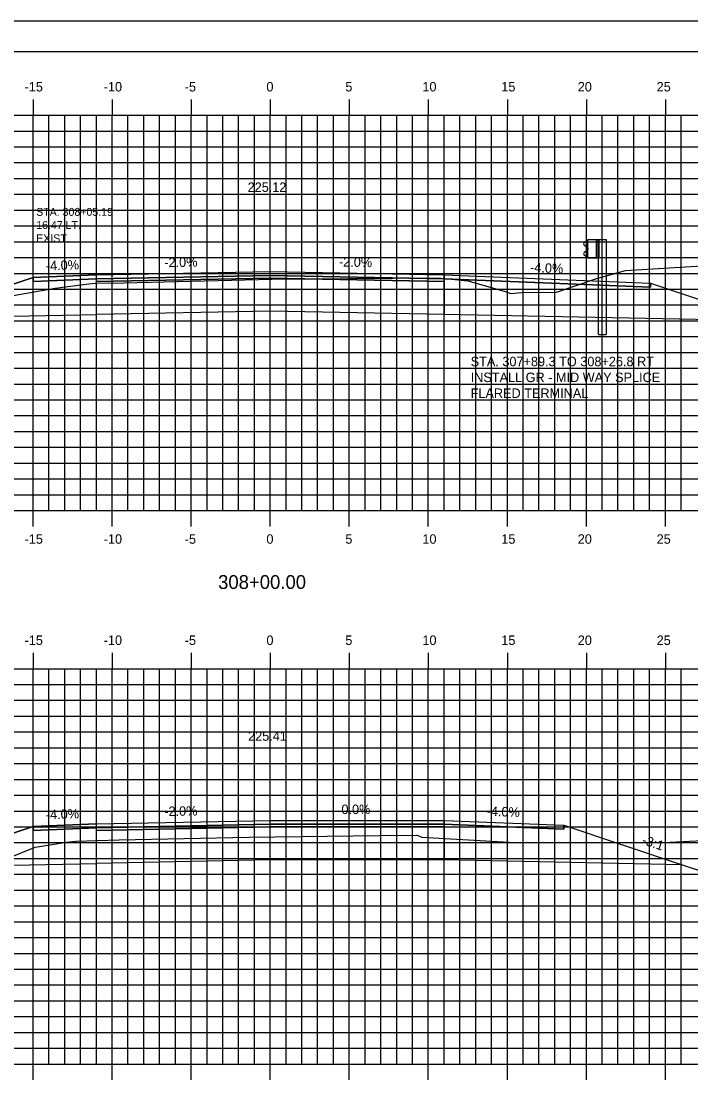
# Model space of a CAD drawing. Extents: x 1137654 to 1137824, y 608981 to 609091.
# Drawn here: x 1137721.7 to 1137764, y 609024.1 to 609091.3 of the extents above; entities that cross this region are included whole.
import ezdxf

# ---------------------------------------------------------------- set-up
doc = ezdxf.new("R2010")
doc.units = 0
for name, color, linetype in [('ANNOTATION', 7, 'Continuous'), ('BORDER', 7, 'Continuous'), ('D_Guardrail_Beam_Lt', 7, 'Continuous'), ('D_Guardrail_Beam_Rt', 7, 'Continuous'), ('D_Roadway_Centerline', 7, 'Continuous'), ('D_Roadway_Centerline_Text', 7, 'Continuous'), ('D_Roadway_Edge_Shoulder', 7, 'Continuous'), ('D_Roadway_Edge_TW', 7, 'Continuous'), ('D_Roadway_Pavement', 7, 'Continuous'), ('D_Roadway_SlopeLines', 7, 'Continuous'), ('D_Roadway_SubGrade', 7, 'Continuous'), ('D_Text_Monospaced', 7, 'Continuous'), ('H_V ANNOTATION', 7, 'Continuous'), ('MAJOR', 7, 'Continuous'), ('MINOR', 7, 'Continuous'), ('PLOT BOUNDARY', 7, 'Continuous'), ('S_Roadway_Centerline', 7, 'Continuous')]:
    doc.layers.add(name, color=color, linetype=linetype)

msp = doc.modelspace()

# ---------------------------------------------------------------- linework, layer by layer
for points in [[(1137703.372, 609073.203), (1137704.622, 609073.195), (1137705.872, 609073.01), (1137707.122, 609072.649), (1137708.372, 609072.113), (1137710.435, 609071.081), (1137714.685, 609072.498), (1137722.408, 609075.072), (1137722.409, 609075.072), (1137726.409, 609075.232), (1137737.409, 609075.452), (1137748.409, 609075.232), (1137761.476, 609074.71), (1137768.621, 609072.328), (1137772.371, 609071.078), (1137780.547, 609075.166), (1137781.797, 609075.675), (1137783.047, 609075.953), (1137784.297, 609075.999), (1137785.547, 609075.814)], [(1137700.848, 609033.177), (1137711.685, 609036.789), (1137714.685, 609037.789), (1137722.408, 609040.363), (1137722.409, 609040.363), (1137726.409, 609040.523), (1137737.409, 609040.743), (1137748.409, 609040.743), (1137755.981, 609040.44), (1137763.476, 609037.942), (1137766.476, 609036.942), (1137769.526, 609038.467), (1137770.776, 609039.018), (1137772.026, 609039.421), (1137773.276, 609039.676), (1137774.526, 609039.784)]]:
    msp.add_lwpolyline(points)
at = {"layer": 'BORDER'}
msp.add_lwpolyline([(1137662.41, 608984.335), (1137822.41, 608984.335), (1137822.41, 609089.335), (1137662.41, 609089.335)], close=True, dxfattribs=at)
at = {"layer": 'D_Guardrail_Beam_Lt'}
for p, q in [((1137757.418, 609077.363), (1137757.274, 609077.263)), ((1137757.508, 609077.384), (1137757.434, 609077.37)), ((1137757.274, 609077.12), (1137757.47, 609076.984)), ((1137757.47, 609076.785), (1137757.274, 609076.649)), ((1137757.274, 609076.506), (1137757.418, 609076.406)), ((1137757.503, 609076.919), (1137757.503, 609076.849)), ((1137757.434, 609076.399), (1137757.508, 609076.384))]:
    msp.add_line(p, q, dxfattribs=at)
for centre, major_axis, start_param, end_param in [((1137757.325, 609077.192), (-0.0877, 0), 5.323254, 7.243116), ((1137757.442, 609077.329), (-0.0417, 0), 4.907132, 5.323254), ((1137757.325, 609076.577), (-0.0877, 0), 5.323254, 7.243116), ((1137757.425, 609076.919), (0.0789, 0), 0, 0.959931), ((1137757.425, 609076.849), (0.0789, 0), 5.323254, 6.283185), ((1137757.442, 609076.44), (-0.0417, 0), 0.959931, 1.376053)]:
    msp.add_ellipse(centre, major_axis=major_axis, ratio=0.995501, start_param=start_param, end_param=end_param, dxfattribs=at)
at = {"layer": 'D_Guardrail_Beam_Rt'}
for p, q in [((1137757.508, 609077.468), (1137758.195, 609077.468)), ((1137757.508, 609076.301), (1137757.508, 609077.468)), ((1137758.029, 609077.468), (1137758.029, 609076.301)), ((1137758.133, 609077.468), (1137758.133, 609076.301)), ((1137758.195, 609077.468), (1137758.666, 609077.468)), ((1137758.195, 609077.468), (1137758.195, 609076.301)), ((1137758.666, 609077.468), (1137758.666, 609071.468)), ((1137758.195, 609076.301), (1137757.508, 609076.301)), ((1137758.175, 609071.468), (1137758.175, 609076.301)), ((1137758.175, 609071.468), (1137758.666, 609071.468))]:
    msp.add_line(p, q, dxfattribs=at)
at = {"layer": 'D_Roadway_Edge_Shoulder'}
for points in [[(1137726.409, 609075.232), (1137722.409, 609075.072), (1137722.409, 609074.822), (1137726.409, 609074.982)], [(1137748.409, 609075.232), (1137761.476, 609074.71), (1137761.476, 609074.46), (1137748.409, 609074.982)], [(1137726.409, 609040.523), (1137722.409, 609040.363), (1137722.409, 609040.113), (1137726.409, 609040.273)], [(1137748.409, 609040.743), (1137755.981, 609040.44), (1137755.981, 609040.19), (1137748.409, 609040.493)]]:
    msp.add_lwpolyline(points, close=True, dxfattribs=at)
at = {"layer": 'D_Roadway_Edge_TW'}
for points in [[(1137726.409, 609074.982), (1137726.409, 609075.232), (1137737.409, 609075.452), (1137748.409, 609075.232), (1137748.409, 609074.982), (1137737.409, 609075.202)], [(1137726.409, 609040.273), (1137726.409, 609040.523), (1137737.409, 609040.743), (1137748.409, 609040.743), (1137748.409, 609040.493), (1137737.409, 609040.493)]]:
    msp.add_lwpolyline(points, close=True, dxfattribs=at)
at = {"layer": 'D_Roadway_Pavement'}
for points in [[(1137726.409, 609074.816), (1137726.409, 609074.982), (1137737.409, 609075.202), (1137748.409, 609074.982), (1137748.409, 609074.816), (1137737.409, 609075.036)], [(1137726.409, 609040.107), (1137726.409, 609040.273), (1137737.409, 609040.493), (1137748.409, 609040.493), (1137748.409, 609040.327), (1137737.409, 609040.327)]]:
    msp.add_lwpolyline(points, close=True, dxfattribs=at)
at = {"layer": 'D_Roadway_SlopeLines'}
msp.add_lwpolyline([(1137763.476, 609037.942), (1137766.476, 609036.942)], dxfattribs=at)
at = {"layer": 'D_Roadway_SubGrade'}
for points in [[(1137726.409, 609074.816), (1137726.409, 609074.982), (1137722.409, 609074.822), (1137722.409, 609075.072), (1137722.408, 609075.072), (1137714.685, 609072.498), (1137726.409, 609072.732)], [(1137726.409, 609072.732), (1137726.409, 609074.816), (1137737.409, 609075.036), (1137748.409, 609074.816), (1137748.409, 609072.732), (1137737.409, 609072.952)], [(1137748.409, 609074.816), (1137748.409, 609074.982), (1137761.476, 609074.46), (1137761.476, 609074.71), (1137761.476, 609074.71), (1137768.621, 609072.328), (1137748.409, 609072.732)], [(1137726.409, 609040.107), (1137726.409, 609040.273), (1137722.409, 609040.113), (1137722.409, 609040.363), (1137722.408, 609040.363), (1137714.685, 609037.789), (1137726.409, 609038.023)], [(1137726.409, 609038.023), (1137726.409, 609040.107), (1137737.409, 609040.327), (1137748.409, 609040.327), (1137748.409, 609038.243), (1137737.409, 609038.243)], [(1137748.409, 609040.327), (1137748.409, 609040.493), (1137755.981, 609040.19), (1137755.981, 609040.44), (1137755.981, 609040.44), (1137763.476, 609037.942), (1137748.409, 609038.243)]]:
    msp.add_lwpolyline(points, close=True, dxfattribs=at)
at = {"layer": 'MAJOR'}
for p, q in [((1137722.409, 609086.337), (1137722.409, 609085.335)), ((1137727.409, 609086.337), (1137727.409, 609085.335)), ((1137732.409, 609086.337), (1137732.409, 609085.335)), ((1137737.409, 609086.337), (1137737.409, 609085.335)), ((1137742.409, 609086.337), (1137742.409, 609085.335)), ((1137747.409, 609086.337), (1137747.409, 609085.335)), ((1137752.409, 609086.337), (1137752.409, 609085.335)), ((1137757.409, 609086.337), (1137757.409, 609085.335)), ((1137762.409, 609086.337), (1137762.409, 609085.335)), ((1137667.409, 609085.335), (1137807.409, 609085.335)), ((1137667.409, 609085.335), (1137807.409, 609085.335)), ((1137722.409, 609060.335), (1137722.409, 609085.335)), ((1137727.409, 609060.335), (1137727.409, 609085.335)), ((1137732.409, 609060.335), (1137732.409, 609085.335)), ((1137737.409, 609060.335), (1137737.409, 609085.335)), ((1137742.409, 609060.335), (1137742.409, 609085.335)), ((1137747.409, 609060.335), (1137747.409, 609085.335)), ((1137752.409, 609060.335), (1137752.409, 609085.335)), ((1137757.409, 609060.335), (1137757.409, 609085.335)), ((1137762.409, 609060.335), (1137762.409, 609085.335)), ((1137667.409, 609080.335), (1137807.409, 609080.335)), ((1137667.409, 609075.335), (1137807.409, 609075.335)), ((1137667.409, 609070.335), (1137807.409, 609070.335)), ((1137667.409, 609065.335), (1137807.409, 609065.335)), ((1137667.409, 609060.335), (1137807.409, 609060.335)), ((1137667.409, 609060.335), (1137807.409, 609060.335)), ((1137722.409, 609059.333), (1137722.409, 609060.335)), ((1137727.409, 609059.333), (1137727.409, 609060.335)), ((1137732.409, 609059.333), (1137732.409, 609060.335)), ((1137737.409, 609059.333), (1137737.409, 609060.335)), ((1137742.409, 609059.333), (1137742.409, 609060.335)), ((1137747.409, 609059.333), (1137747.409, 609060.335)), ((1137752.409, 609059.333), (1137752.409, 609060.335)), ((1137757.409, 609059.333), (1137757.409, 609060.335)), ((1137762.409, 609059.333), (1137762.409, 609060.335)), ((1137722.409, 609051.337), (1137722.409, 609050.335)), ((1137727.409, 609051.337), (1137727.409, 609050.335)), ((1137732.409, 609051.337), (1137732.409, 609050.335)), ((1137737.409, 609051.337), (1137737.409, 609050.335)), ((1137742.409, 609051.337), (1137742.409, 609050.335)), ((1137747.409, 609051.337), (1137747.409, 609050.335)), ((1137752.409, 609051.337), (1137752.409, 609050.335)), ((1137757.409, 609051.337), (1137757.409, 609050.335)), ((1137762.409, 609051.337), (1137762.409, 609050.335)), ((1137667.409, 609050.335), (1137807.409, 609050.335)), ((1137667.409, 609050.335), (1137807.409, 609050.335)), ((1137722.409, 609025.335), (1137722.409, 609050.335)), ((1137727.409, 609025.335), (1137727.409, 609050.335)), ((1137732.409, 609025.335), (1137732.409, 609050.335)), ((1137737.409, 609025.335), (1137737.409, 609050.335)), ((1137742.409, 609025.335), (1137742.409, 609050.335)), ((1137747.409, 609025.335), (1137747.409, 609050.335)), ((1137752.409, 609025.335), (1137752.409, 609050.335)), ((1137757.409, 609025.335), (1137757.409, 609050.335)), ((1137762.409, 609025.335), (1137762.409, 609050.335)), ((1137667.409, 609045.335), (1137807.409, 609045.335)), ((1137667.409, 609040.335), (1137807.409, 609040.335)), ((1137667.409, 609035.335), (1137807.409, 609035.335)), ((1137667.409, 609030.335), (1137807.409, 609030.335)), ((1137667.409, 609025.335), (1137807.409, 609025.335)), ((1137667.409, 609025.335), (1137807.409, 609025.335)), ((1137722.409, 609024.333), (1137722.409, 609025.335)), ((1137727.409, 609024.333), (1137727.409, 609025.335)), ((1137732.409, 609024.333), (1137732.409, 609025.335)), ((1137737.409, 609024.333), (1137737.409, 609025.335)), ((1137742.409, 609024.333), (1137742.409, 609025.335)), ((1137747.409, 609024.333), (1137747.409, 609025.335)), ((1137752.409, 609024.333), (1137752.409, 609025.335)), ((1137757.409, 609024.333), (1137757.409, 609025.335)), ((1137762.409, 609024.333), (1137762.409, 609025.335))]:
    msp.add_line(p, q, dxfattribs=at)
at = {"layer": 'MINOR'}
for p, q in [((1137723.409, 609060.335), (1137723.409, 609085.335)), ((1137724.409, 609060.335), (1137724.409, 609085.335)), ((1137725.409, 609060.335), (1137725.409, 609085.335)), ((1137726.409, 609060.335), (1137726.409, 609085.335)), ((1137728.409, 609060.335), (1137728.409, 609085.335)), ((1137729.409, 609060.335), (1137729.409, 609085.335)), ((1137730.409, 609060.335), (1137730.409, 609085.335)), ((1137731.409, 609060.335), (1137731.409, 609085.335)), ((1137733.409, 609060.335), (1137733.409, 609085.335)), ((1137734.409, 609060.335), (1137734.409, 609085.335)), ((1137735.409, 609060.335), (1137735.409, 609085.335)), ((1137736.409, 609060.335), (1137736.409, 609085.335)), ((1137738.409, 609060.335), (1137738.409, 609085.335)), ((1137739.409, 609060.335), (1137739.409, 609085.335)), ((1137740.409, 609060.335), (1137740.409, 609085.335)), ((1137741.409, 609060.335), (1137741.409, 609085.335)), ((1137743.409, 609060.335), (1137743.409, 609085.335)), ((1137744.409, 609060.335), (1137744.409, 609085.335)), ((1137745.409, 609060.335), (1137745.409, 609085.335)), ((1137746.409, 609060.335), (1137746.409, 609085.335)), ((1137748.409, 609060.335), (1137748.409, 609085.335)), ((1137749.409, 609060.335), (1137749.409, 609085.335)), ((1137750.409, 609060.335), (1137750.409, 609085.335)), ((1137751.409, 609060.335), (1137751.409, 609085.335)), ((1137753.409, 609060.335), (1137753.409, 609085.335)), ((1137754.409, 609060.335), (1137754.409, 609085.335)), ((1137755.409, 609060.335), (1137755.409, 609085.335)), ((1137756.409, 609060.335), (1137756.409, 609085.335)), ((1137758.409, 609060.335), (1137758.409, 609085.335)), ((1137759.409, 609060.335), (1137759.409, 609085.335)), ((1137760.409, 609060.335), (1137760.409, 609085.335)), ((1137761.409, 609060.335), (1137761.409, 609085.335)), ((1137763.409, 609060.335), (1137763.409, 609085.335)), ((1137667.409, 609084.335), (1137807.409, 609084.335)), ((1137667.409, 609083.335), (1137807.409, 609083.335)), ((1137667.409, 609082.335), (1137807.409, 609082.335)), ((1137667.409, 609081.335), (1137807.409, 609081.335)), ((1137667.409, 609079.335), (1137807.409, 609079.335)), ((1137667.409, 609078.335), (1137807.409, 609078.335)), ((1137667.409, 609077.335), (1137807.409, 609077.335)), ((1137667.409, 609076.335), (1137807.409, 609076.335)), ((1137667.409, 609074.335), (1137807.409, 609074.335)), ((1137667.409, 609073.335), (1137807.409, 609073.335)), ((1137667.409, 609072.335), (1137807.409, 609072.335)), ((1137667.409, 609071.335), (1137807.409, 609071.335)), ((1137667.409, 609069.335), (1137807.409, 609069.335)), ((1137667.409, 609068.335), (1137807.409, 609068.335)), ((1137667.409, 609067.335), (1137807.409, 609067.335)), ((1137667.409, 609066.335), (1137807.409, 609066.335)), ((1137667.409, 609064.335), (1137807.409, 609064.335)), ((1137667.409, 609063.335), (1137807.409, 609063.335)), ((1137667.409, 609062.335), (1137807.409, 609062.335)), ((1137667.409, 609061.335), (1137807.409, 609061.335)), ((1137723.409, 609025.335), (1137723.409, 609050.335)), ((1137724.409, 609025.335), (1137724.409, 609050.335)), ((1137725.409, 609025.335), (1137725.409, 609050.335)), ((1137726.409, 609025.335), (1137726.409, 609050.335)), ((1137728.409, 609025.335), (1137728.409, 609050.335)), ((1137729.409, 609025.335), (1137729.409, 609050.335)), ((1137730.409, 609025.335), (1137730.409, 609050.335)), ((1137731.409, 609025.335), (1137731.409, 609050.335)), ((1137733.409, 609025.335), (1137733.409, 609050.335)), ((1137734.409, 609025.335), (1137734.409, 609050.335)), ((1137735.409, 609025.335), (1137735.409, 609050.335)), ((1137736.409, 609025.335), (1137736.409, 609050.335)), ((1137738.409, 609025.335), (1137738.409, 609050.335)), ((1137739.409, 609025.335), (1137739.409, 609050.335)), ((1137740.409, 609025.335), (1137740.409, 609050.335)), ((1137741.409, 609025.335), (1137741.409, 609050.335)), ((1137743.409, 609025.335), (1137743.409, 609050.335)), ((1137744.409, 609025.335), (1137744.409, 609050.335)), ((1137745.409, 609025.335), (1137745.409, 609050.335)), ((1137746.409, 609025.335), (1137746.409, 609050.335)), ((1137748.409, 609025.335), (1137748.409, 609050.335)), ((1137749.409, 609025.335), (1137749.409, 609050.335)), ((1137750.409, 609025.335), (1137750.409, 609050.335)), ((1137751.409, 609025.335), (1137751.409, 609050.335)), ((1137753.409, 609025.335), (1137753.409, 609050.335)), ((1137754.409, 609025.335), (1137754.409, 609050.335)), ((1137755.409, 609025.335), (1137755.409, 609050.335)), ((1137756.409, 609025.335), (1137756.409, 609050.335)), ((1137758.409, 609025.335), (1137758.409, 609050.335)), ((1137759.409, 609025.335), (1137759.409, 609050.335)), ((1137760.409, 609025.335), (1137760.409, 609050.335)), ((1137761.409, 609025.335), (1137761.409, 609050.335)), ((1137763.409, 609025.335), (1137763.409, 609050.335)), ((1137667.409, 609049.335), (1137807.409, 609049.335)), ((1137667.409, 609048.335), (1137807.409, 609048.335)), ((1137667.409, 609047.335), (1137807.409, 609047.335)), ((1137667.409, 609046.335), (1137807.409, 609046.335)), ((1137667.409, 609044.335), (1137807.409, 609044.335)), ((1137667.409, 609043.335), (1137807.409, 609043.335)), ((1137667.409, 609042.335), (1137807.409, 609042.335)), ((1137667.409, 609041.335), (1137807.409, 609041.335)), ((1137667.409, 609039.335), (1137807.409, 609039.335)), ((1137667.409, 609038.335), (1137807.409, 609038.335)), ((1137667.409, 609037.335), (1137807.409, 609037.335)), ((1137667.409, 609036.335), (1137807.409, 609036.335)), ((1137667.409, 609034.335), (1137807.409, 609034.335)), ((1137667.409, 609033.335), (1137807.409, 609033.335)), ((1137667.409, 609032.335), (1137807.409, 609032.335)), ((1137667.409, 609031.335), (1137807.409, 609031.335)), ((1137667.409, 609029.335), (1137807.409, 609029.335)), ((1137667.409, 609028.335), (1137807.409, 609028.335)), ((1137667.409, 609027.335), (1137807.409, 609027.335)), ((1137667.409, 609026.335), (1137807.409, 609026.335))]:
    msp.add_line(p, q, dxfattribs=at)
at = {"layer": 'PLOT BOUNDARY'}
msp.add_lwpolyline([(1137654.316, 608981.276), (1137824.316, 608981.276), (1137824.316, 609091.276), (1137654.316, 609091.276)], close=True, dxfattribs=at)
at = {"layer": 'S_Roadway_Centerline'}
for points in [[(1137667.409, 609069.72), (1137676.984, 609070.875), (1137687.338, 609071.833), (1137697.235, 609072.821), (1137703.411, 609073.206), (1137707.864, 609073.49), (1137714.699, 609072.26), (1137721.151, 609073.928), (1137723.806, 609074.396), (1137725.924, 609074.671), (1137726.331, 609074.705), (1137728.139, 609074.727), (1137737.517, 609074.967), (1137739.695, 609074.987), (1137747.943, 609075.052), (1137748.455, 609075.015), (1137749.9, 609074.851), (1137752.206, 609074.198), (1137752.624, 609074.067), (1137753.307, 609074.115), (1137755.515, 609074.146), (1137758.076, 609075.005), (1137759.89, 609075.513), (1137770.942, 609076.182)], [(1137667.409, 609031.673), (1137680.898, 609032.377), (1137683.689, 609032.524), (1137701.957, 609033.219), (1137704.697, 609033.873), (1137715.818, 609036.339), (1137722.54, 609039.054), (1137724.51, 609039.355), (1137725.115, 609039.434), (1137727.86, 609039.504), (1137736.081, 609039.689), (1137744.308, 609039.789), (1137746.709, 609039.808), (1137746.997, 609039.677), (1137753.261, 609039.323), (1137761.612, 609039.363), (1137761.894, 609039.317), (1137766.806, 609039.577), (1137782.426, 609039.995), (1137793.11, 609040.238), (1137799.729, 609040.508), (1137807.409, 609040.788)]]:
    msp.add_lwpolyline(points, dxfattribs=at)

# ---------------------------------------------------------------- texts
at = {"layer": 'ANNOTATION'}
for s, rotation, p in [('-4.0%', 2.29061, (1137723.225, 609075.506)), ('-2.0%', 1.14576, (1137730.712, 609075.718)), ('-2.0%', 358.85424, (1137741.752, 609075.766)), ('-4.0%', 357.70939, (1137753.839, 609075.416)), ('-2.0%', 1.14576, (1137730.712, 609041.01)), ('-4.0%', 357.70939, (1137751.091, 609041.037)), ('-4.0%', 2.29061, (1137723.225, 609040.797)), ('-3:1', 341.56522, (1137760.878, 609039.262))]:
    msp.add_text(s, height=0.6, rotation=rotation, dxfattribs=at).set_placement(p)
for s, p in [('STA. 307+89.3 TO 308+26.8 RT', (1137750.089, 609069.46)), ('INSTALL GR - MID WAY SPLICE', (1137750.089, 609068.458)), ('FLARED TERMINAL', (1137750.089, 609067.456)), ('0.0%', (1137741.914, 609041.143))]:
    msp.add_text(s, height=0.6, dxfattribs=at).set_placement(p)
at = {"layer": 'D_Roadway_Centerline'}
for s, p in [('C', (1137737.404, 609075.452)), ('L', (1137737.409, 609075.445)), ('C', (1137737.404, 609040.743)), ('L', (1137737.409, 609040.736))]:
    msp.add_text(s, height=0.0146, dxfattribs=at).set_placement(p)
at = {"layer": 'D_Roadway_Centerline_Text'}
for s, p in [('225.12', (1137735.978, 609080.484)), ('225.41', (1137736.007, 609045.775))]:
    msp.add_text(s, height=0.6, dxfattribs=at).set_placement(p)
at = {"layer": 'D_Text_Monospaced'}
for s, height, p in [('STA. 308+05.19', 0.49998, (1137722.603, 609078.972)), ('16.47 LT.', 0.5, (1137722.603, 609078.138)), ('EXIST. ', 0.5, (1137722.603, 609077.298))]:
    msp.add_text(s, height=height, dxfattribs=at).set_placement(p)
at = {"layer": 'H_V ANNOTATION'}
for s, height, p in [('-15', 0.6, (1137721.866, 609086.835)), ('-10', 0.6, (1137726.874, 609086.835)), ('-5', 0.6, (1137732, 609086.835)), ('0', 0.6, (1137737.168, 609086.835)), ('5', 0.6, (1137742.16, 609086.835)), ('10', 0.6, (1137747.035, 609086.835)), ('15', 0.6, (1137752.027, 609086.835)), ('20', 0.6, (1137756.863, 609086.835)), ('25', 0.6, (1137761.855, 609086.835)), ('-15', 0.6, (1137721.866, 609058.235)), ('-10', 0.6, (1137726.874, 609058.235)), ('-5', 0.6, (1137732, 609058.235)), ('0', 0.6, (1137737.168, 609058.235)), ('5', 0.6, (1137742.16, 609058.235)), ('10', 0.6, (1137747.035, 609058.235)), ('15', 0.6, (1137752.027, 609058.235)), ('20', 0.6, (1137756.863, 609058.235)), ('25', 0.6, (1137761.855, 609058.235)), ('308+00.00', 0.875, (1137734.109, 609055.378)), ('-15', 0.6, (1137721.866, 609051.835)), ('-10', 0.6, (1137726.874, 609051.835)), ('-5', 0.6, (1137732, 609051.835)), ('0', 0.6, (1137737.168, 609051.835)), ('5', 0.6, (1137742.16, 609051.835)), ('10', 0.6, (1137747.035, 609051.835)), ('15', 0.6, (1137752.027, 609051.835)), ('20', 0.6, (1137756.863, 609051.835)), ('25', 0.6, (1137761.855, 609051.835))]:
    msp.add_text(s, height=height, dxfattribs=at).set_placement(p)
at = {"layer": 'S_Roadway_Centerline'}
for s, p in [('C', (1137737.511, 609074.967)), ('L', (1137737.517, 609074.959)), ('L', (1137736.072, 609039.682)), ('C', (1137736.076, 609039.689))]:
    msp.add_text(s, height=0.0146, dxfattribs=at).set_placement(p)

doc.saveas('drawing.dxf')
